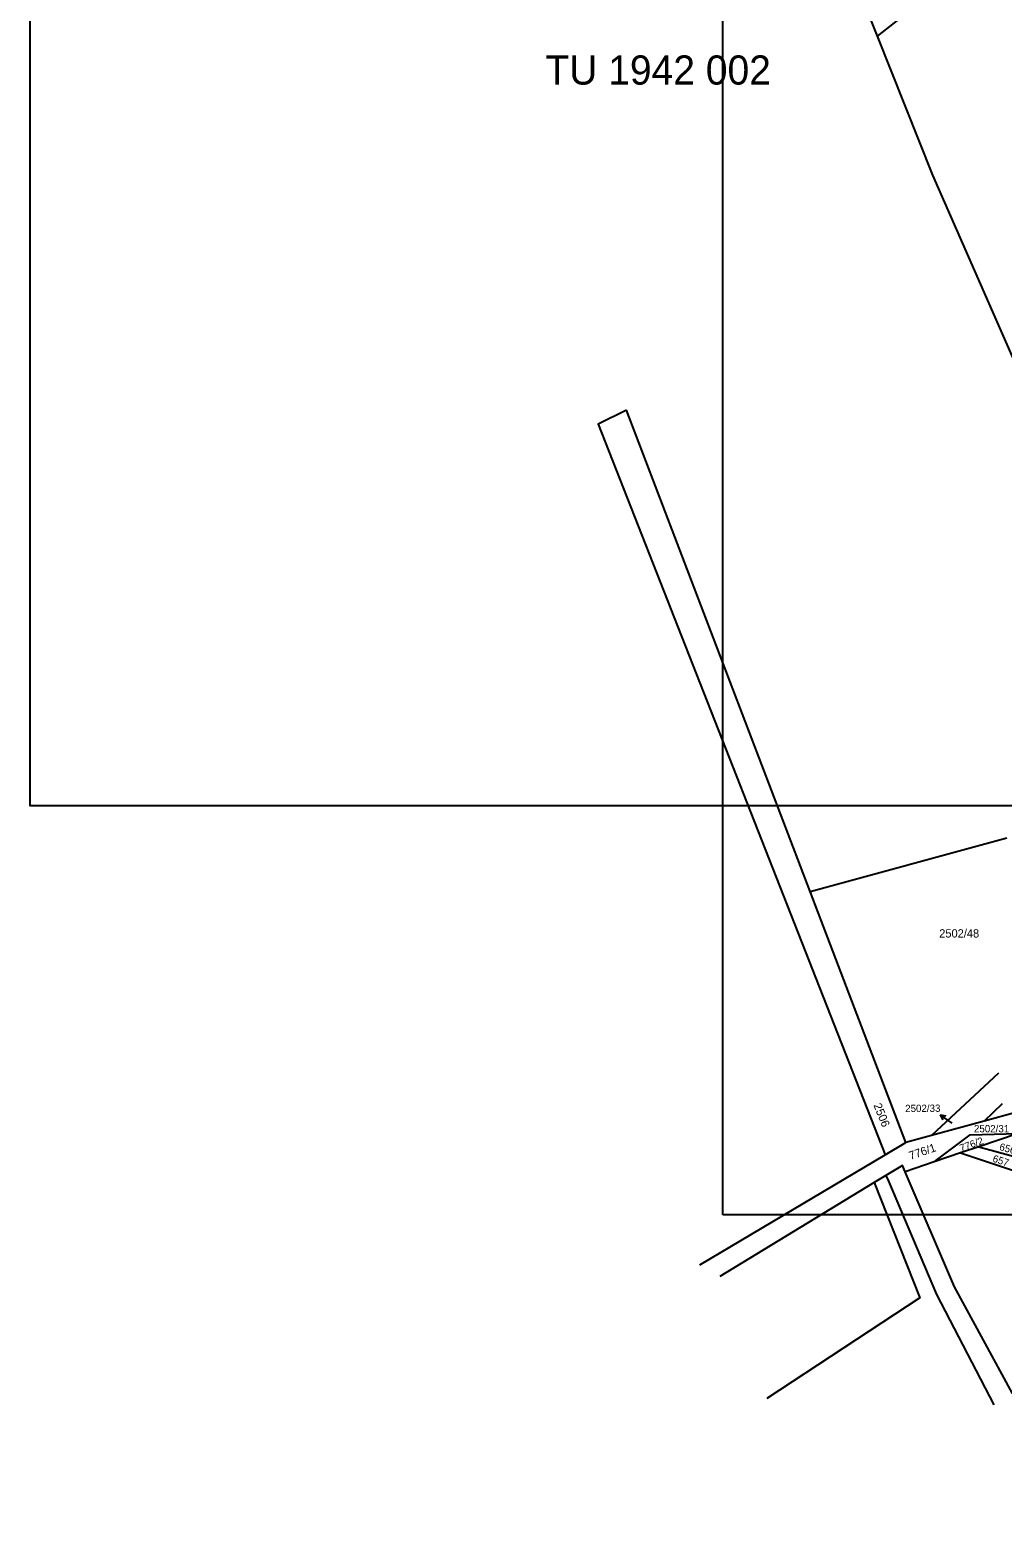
# Model space of a CAD drawing. Extents: x -558500 to -557517, y -1073973 to -1073051.
# Drawn here: x -558500 to -558299.9, y -1073850.5 to -1073540.5 of the extents above; entities that cross this region are included whole.
import ezdxf

# ---------------------------------------------------------------- set-up
doc = ezdxf.new("R2010")
doc.units = 0
for name, color, linetype in [('Default', 7, 'Continuous'), ('Hranice parcel', 7, 'Continuous'), ('Parcelní čísla', 7, 'Continuous'), ('Pop  PČ popisy', 7, 'Continuous'), ('Vrstva 1', 7, 'Continuous'), ('Vrstva 2', 7, 'Continuous')]:
    doc.layers.add(name, color=color, linetype=linetype)

msp = doc.modelspace()

# ---------------------------------------------------------------- linework, layer by layer
at = {"layer": 'Default'}
msp.add_lwpolyline([(-557909.21, -1073700), (-558500, -1073700), (-558500, -1073200), (-557800, -1073200), (-557800, -1073567.6)], dxfattribs=at)
at = {"layer": 'Hranice parcel'}
for p, q in [((-558325.69, -1073541.72), (-558259.89, -1073489.61)), ((-558325.69, -1073541.72), (-558339.52, -1073506.95)), ((-558314.35, -1073570.26), (-558325.69, -1073541.72)), ((-558286.79, -1073633.11), (-558314.35, -1073570.26)), ((-558339.57, -1073717.56), (-558377.34, -1073618.64)), ((-558339.57, -1073717.56), (-558299.09, -1073706.57)), ((-558319.85, -1073769.2), (-558339.57, -1073717.56)), ((-558300.8, -1073754.92), (-558314.63, -1073767.78)), ((-558300.06, -1073761.28), (-558303.78, -1073764.84)), ((-558297.22, -1073763.06), (-558303.78, -1073764.84)), ((-558303.78, -1073764.84), (-558314.63, -1073767.78)), ((-558296.74, -1073767.33), (-558304.84, -1073770.08)), ((-558324.15, -1073771.75), (-558319.85, -1073769.2)), ((-558314.63, -1073767.78), (-558319.85, -1073769.2)), ((-558304.84, -1073770.08), (-558308.63, -1073771.36)), ((-558304.84, -1073770.08), (-558295.26, -1073772.72)), ((-558362.27, -1073794.36), (-558324.15, -1073771.75)), ((-558314.07, -1073773.21), (-558319.99, -1073775.22)), ((-558308.63, -1073771.36), (-558314.07, -1073773.21)), ((-558308.63, -1073771.36), (-558296.72, -1073775.29)), ((-558323.98, -1073776), (-558326.38, -1073777.46)), ((-558326.38, -1073777.46), (-558358.14, -1073796.74))]:
    msp.add_line(p, q, dxfattribs=at)
for points in [[(-558377.34, -1073618.64), (-558383.17, -1073621.49), (-558324.15, -1073771.75)], [(-558314.07, -1073773.21), (-558306.66, -1073767.6), (-558296.74, -1073767.33)], [(-558319.99, -1073775.22), (-558320.55, -1073773.92), (-558323.98, -1073776)], [(-558323.98, -1073776), (-558323.47, -1073777.18), (-558313.56, -1073800.48), (-558301.76, -1073823.12)], [(-558278.21, -1073850.5), (-558297.93, -1073820.82), (-558309.88, -1073798.91), (-558319.99, -1073775.22)], [(-558326.38, -1073777.46), (-558317.03, -1073801.15), (-558348.5, -1073821.82)]]:
    msp.add_lwpolyline(points, dxfattribs=at)
at = {"layer": 'Pop  PČ popisy'}
for p, q in [((-558310.33, -1073765.25), (-558312.78, -1073763.52)), ((-558312.78, -1073763.52), (-558311.67, -1073763.69)), ((-558312.78, -1073763.52), (-558312.25, -1073764.51))]:
    msp.add_line(p, q, dxfattribs=at)
at = {"layer": 'Vrstva 1'}
for p, q in [((-558357.53, -1073784.09), (-558357.53, -1073190.09)), ((-557516.53, -1073784.09), (-558357.53, -1073784.09))]:
    msp.add_line(p, q, dxfattribs=at)

# ---------------------------------------------------------------- texts
at = {"layer": 'Parcelní čísla'}
for s, height, p in [('2502/48', 1.7, (-558313.01, -1073727.05)), ('2502/31', 1.5, (-558305.86, -1073767.11))]:
    msp.add_text(s, height=height, dxfattribs=at).set_placement(p)
for s, height, rotation, p in [('2506', 1.7, 292, (-558326.57, -1073761.52)), ('2502/33', 1.5, 0.4465, (-558320.01, -1073762.95)), ('776/1', 1.7, 18.8548, (-558318.91, -1073772.79)), ('776/2', 1.5, 20, (-558308.48, -1073771.15)), ('656', 1.5, 344, (-558300.76, -1073770.72)), ('657', 1.5, 342, (-558302.15, -1073773.13))]:
    msp.add_text(s, height=height, rotation=rotation, dxfattribs=at).set_placement(p)
at = {"layer": 'Vrstva 2'}
msp.add_text('TU 1942 002', height=6, dxfattribs=at).set_placement((-558394.02, -1073551.66))

doc.saveas('drawing.dxf')
